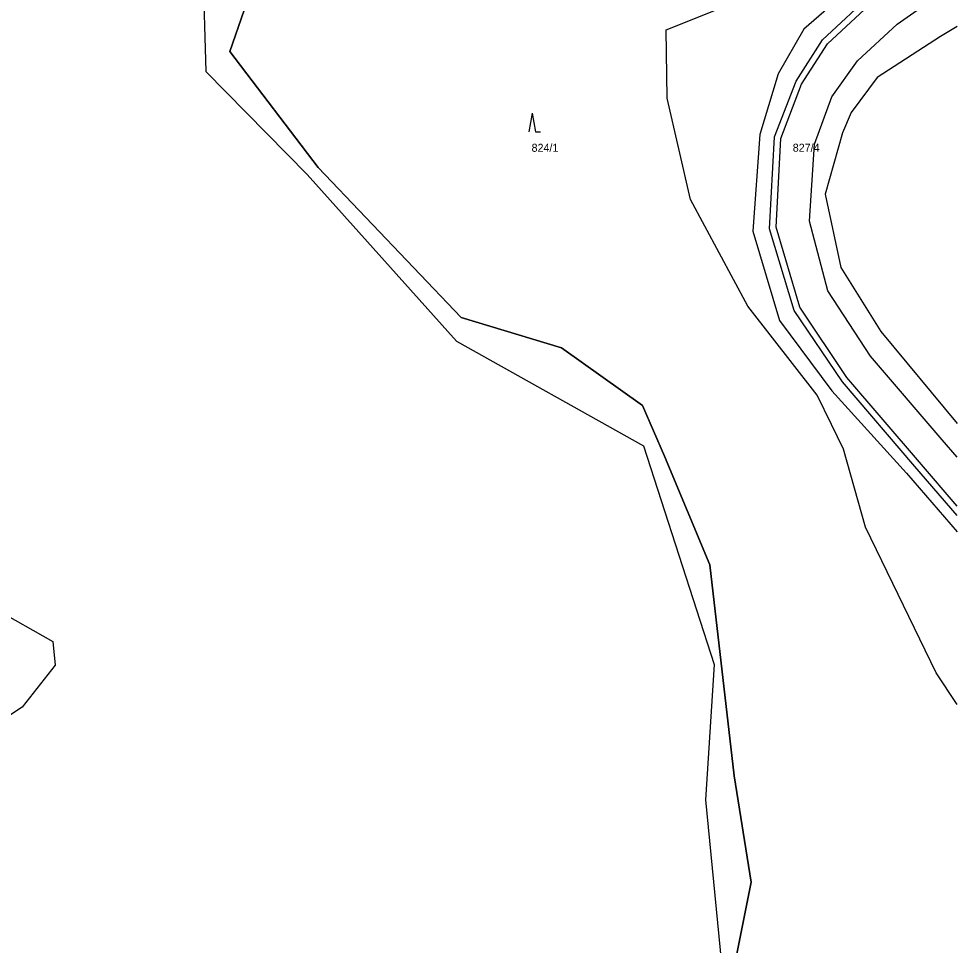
# Model space of a CAD drawing. Extents: x -737240 to -735272, y -1119606 to -1117878.
# Drawn here: x -735471.5 to -735272.2, y -1118491.3 to -1118294.6 of the extents above; entities that cross this region are included whole.
import ezdxf

# ---------------------------------------------------------------- set-up
doc = ezdxf.new("R2010")
doc.units = 0
for name, color, linetype in [('Level 1', 7, 'Continuous'), ('Level 13', 7, 'Continuous'), ('Level 18', 7, 'Continuous'), ('Level 25', 7, 'Continuous'), ('Level 4', 7, 'Continuous')]:
    doc.layers.add(name, color=color, linetype=linetype)

msp = doc.modelspace()

# ---------------------------------------------------------------- linework, layer by layer
at = {"layer": 'Level 1'}
for points in [[(-735272.215, -1118235.352), (-735293.73, -1118244.25), (-735318.8, -1118248.55), (-735372.51, -1118255.8), (-735418.29, -1118267.78), (-735432.38, -1118283.91), (-735431.72, -1118305.77), (-735410.26, -1118327.63), (-735378.55, -1118363.01), (-735338.79, -1118385.27), (-735323.79, -1118431.69), (-735325.65, -1118460.46), (-735322.24, -1118495.31), (-735329.74, -1118504.27)], [(-735320.79, -1118502.01), (-735316, -1118477.93), (-735319.58, -1118455.39), (-735324.75, -1118410.55), (-735334.33, -1118387.43), (-735339.07, -1118376.71), (-735356.26, -1118364.47), (-735377.56, -1118357.98), (-735407.91, -1118326.17), (-735426.65, -1118301.52), (-735417.49, -1118275.12), (-735407.21, -1118269.69), (-735388.3, -1118264.58), (-735358.65, -1118259.95), (-735317.23, -1118255.09), (-735295.06, -1118246.97), (-735272.215, -1118239.048)], [(-735272.215, -1118239.048), (-735295.06, -1118246.97), (-735317.23, -1118255.09), (-735358.65, -1118259.95), (-735388.3, -1118264.58), (-735407.21, -1118269.69), (-735417.49, -1118275.12), (-735426.65, -1118301.52), (-735407.91, -1118326.17), (-735377.56, -1118357.98), (-735356.26, -1118364.47), (-735339.07, -1118376.71), (-735334.33, -1118387.43), (-735324.75, -1118410.55), (-735319.58, -1118455.39), (-735316, -1118477.93), (-735320.79, -1118502.01)], [(-735272.215, -1118440.225), (-735276.71, -1118433.48), (-735291.7, -1118402.57), (-735296.36, -1118385.95), (-735298.9, -1118380.74), (-735301.95, -1118374.49), (-735316.69, -1118355.57), (-735328.83, -1118332.98), (-735333.78, -1118311.44), (-735334.01, -1118296.9), (-735310.42, -1118287.41), (-735305.85, -1118285.57), (-735292.51, -1118286)], [(-735292.51, -1118286), (-735292.57, -1118286.04), (-735304.75, -1118296.77), (-735310.25, -1118306.23), (-735311.37, -1118310), (-735314.09, -1118319.12), (-735315.58, -1118339.66), (-735309.98, -1118358.63), (-735298.87, -1118373.57), (-735282.99, -1118391.11), (-735272.215, -1118403.546)], [(-735272.215, -1118296.166), (-735275.74, -1118298.34), (-735289.23, -1118307.06), (-735294.73, -1118314.44), (-735296.6, -1118318.82), (-735300.23, -1118331.84), (-735296.94, -1118347.38), (-735288.42, -1118360.97), (-735272.215, -1118380.553)], [(-735512.21, -1118394.81), (-735508.12, -1118396.15), (-735501.99, -1118401.88), (-735485.81, -1118415.51), (-735476.52, -1118419.89), (-735464.25, -1118426.82), (-735463.73, -1118431.87), (-735470.75, -1118440.77), (-735483.25, -1118449), (-735503.61, -1118463.49)]]:
    msp.add_lwpolyline(points, dxfattribs=at)
at = {"layer": 'Level 13'}
for points in [[(-735272.215, -1118239.048), (-735295.06, -1118246.97), (-735317.23, -1118255.09), (-735358.65, -1118259.95), (-735388.3, -1118264.58), (-735407.21, -1118269.69), (-735417.49, -1118275.12), (-735426.65, -1118301.52), (-735407.91, -1118326.17), (-735377.56, -1118357.98), (-735356.26, -1118364.47), (-735339.07, -1118376.71), (-735334.33, -1118387.43), (-735324.75, -1118410.55), (-735319.58, -1118455.39), (-735316, -1118477.93), (-735320.79, -1118502.01), (-735332.63, -1118511.79)], [(-735417.49, -1118275.12), (-735426.65, -1118301.52), (-735407.91, -1118326.17), (-735377.56, -1118357.98), (-735356.26, -1118364.47), (-735339.07, -1118376.71), (-735334.33, -1118387.43), (-735324.75, -1118410.55), (-735319.58, -1118455.39), (-735316, -1118477.93), (-735320.79, -1118502.01)]]:
    msp.add_lwpolyline(points, dxfattribs=at)
at = {"layer": 'Level 25'}
for p, q in [((-735362.452, -1118314.599), (-735363.185, -1118318.599)), ((-735362.452, -1118314.599), (-735361.719, -1118318.599)), ((-735361.719, -1118318.599), (-735360.719, -1118318.599))]:
    msp.add_line(p, q, dxfattribs=at)
at = {"layer": 'Level 4'}
for points in [[(-735272.215, -1118400.074), (-735281.2, -1118389.67), (-735296.58, -1118371.7), (-735306.82, -1118356.55), (-735312.05, -1118339.16), (-735310.99, -1118319.62), (-735306.44, -1118307.82), (-735300.82, -1118299.05), (-735289.82, -1118288.75), (-735272.215, -1118276.309)], [(-735272.215, -1118398.051), (-735280.24, -1118388.77), (-735295.66, -1118370.74), (-735305.63, -1118355.81), (-735310.69, -1118338.79), (-735309.66, -1118319.96), (-735305.25, -1118308.43), (-735299.78, -1118299.91), (-735288.96, -1118289.73), (-735272.215, -1118277.928)], [(-735272.215, -1118387.708), (-735275.4, -1118384.01), (-735290.61, -1118366.22), (-735299.66, -1118352.37), (-735303.58, -1118337.54), (-735302.49, -1118321.2), (-735298.83, -1118311.15), (-735293.41, -1118303.47), (-735284.95, -1118295.71), (-735272.215, -1118286.687)]]:
    msp.add_lwpolyline(points, dxfattribs=at)

# ---------------------------------------------------------------- texts
at = {"layer": 'Level 18'}
for s, p in [('824/1', (-735362.585, -1118322.81)), ('827/4', (-735307.135, -1118322.8))]:
    msp.add_text(s, height=1.7, dxfattribs=at).set_placement(p)

doc.saveas('drawing.dxf')
